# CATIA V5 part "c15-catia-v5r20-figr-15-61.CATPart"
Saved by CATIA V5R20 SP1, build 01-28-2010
Part number: Part1
Bounding box of the stored display mesh (mm): x -56.905 to 119.887, y -33.101 to 33.101, z 0 to 1
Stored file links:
  D:\v5_r20\psrt_files_downloaded\c15\c15-catia-v5r20-figr-15-61.CATPart
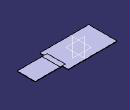
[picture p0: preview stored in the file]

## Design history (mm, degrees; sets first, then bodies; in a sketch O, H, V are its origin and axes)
SheetMetalParameters1: Thickness 1, BendRadius 7, KFactor 0.5 {= log(min(100,max(20*SheetMetalParameters1.BendRadius,SheetMetalParameters1.Thickness)/SheetMetalParameters1.Thickness))/log(100)/2}, ReliefRadialLength 1, ReliefAxialLength 2, MinimumBendRadius 0
Body1 (main body)
  Sketch1 on xy-plane, origin (0, 0, 0), H (1, 0, 0), V (0, 1, 0)
    line L1 (-56.9047, 33.1006) -> (56.9047, 33.1006)
    line L2 (56.9047, 33.1006) -> (56.9047, -33.1006)
    line L3 (56.9047, -33.1006) -> (-56.9047, -33.1006)
    line L4 (-56.9047, -33.1006) -> (-56.9047, 33.1006)
    horizontal: L1 H, L3 H
    vertical: L2 V, L4 V
    symmetry: L1 L3 H, L4 L2 V
  Wall1: Thickness 1, Profile Sketch1
  d_NewWallOnEdge1: NewWallOnEdge_Edge edge [face of Wall1 | face of Wall1], NewWallOnEdge_Length 66.2011, NewWallOnEdge_HeightLimitOffset 0, NewWallOnEdge_WidthOffset1 -10, NewWallOnEdge_WidthOffset2 -14, NewWallOnEdge_Angle 90, NewWallOnEdge_BendRadiusValue 7 {= SheetMetalParameters1.BendRadius}, NewWallOnEdge_BendTable SheetMetalParameters1, KFacteur 0.5 {= log(min(100,max(20*d_NewWallOnEdge1.Radius,SheetMetalParameters1.Thickness)/SheetMetalParameters1.Thickness))/log(100)/2}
